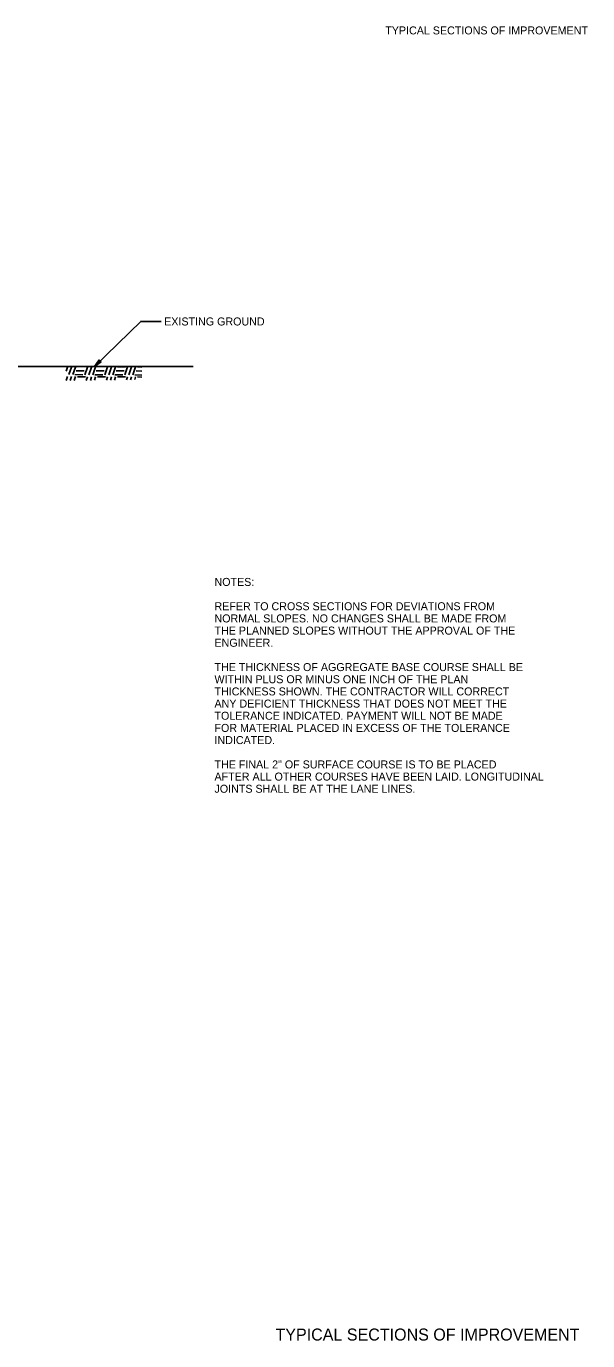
# Model space of a CAD drawing. Extents: x 1824008 to 1828864, y 689441 to 689870.
# Drawn here: x 1828822.3 to 1828864.4, y 689441.4 to 689539.9 of the extents above; entities that cross this region are included whole.
import ezdxf

# ---------------------------------------------------------------- set-up
doc = ezdxf.new("R2010")
doc.units = 0
for name, color, linetype in [('1', 7, 'Continuous'), ('19', 7, 'Continuous'), ('42', 7, 'Continuous'), ('R_Draft', 7, 'Continuous')]:
    doc.layers.add(name, color=color, linetype=linetype)

msp = doc.modelspace()

# ---------------------------------------------------------------- linework, layer by layer
at = {"layer": '1'}
for p, q in [((1828827.765, 689514.917), (1828827.406, 689514.426)), ((1828827.794, 689514.881), (1828827.511, 689514.548)), ((1828827.91, 689514.767), (1828827.765, 689514.917)), ((1828804.735, 689514.422), (1828834.812, 689514.422)), ((1828827.406, 689514.426), (1828827.91, 689514.767)), ((1828827.527, 689514.528), (1828827.869, 689514.802))]:
    msp.add_line(p, q, dxfattribs=at)
msp.add_lwpolyline([(1828832.42, 689517.791), (1828830.882, 689517.793), (1828827.407, 689514.425)], dxfattribs=at)
at = {"layer": '42'}
for p, q in [((1828825.28, 689514.066), (1828825.384, 689514.372)), ((1828825.492, 689513.804), (1828825.683, 689514.368)), ((1828825.792, 689513.803), (1828825.982, 689514.364)), ((1828826.043, 689514.101), (1828826.643, 689514.098)), ((1828826.692, 689513.798), (1828826.885, 689514.369)), ((1828826.992, 689513.797), (1828827.188, 689514.374)), ((1828827.292, 689513.795), (1828827.49, 689514.378)), ((1828827.543, 689514.094), (1828828.143, 689514.091)), ((1828828.192, 689513.79), (1828828.395, 689514.389)), ((1828828.242, 689514.39), (1828828.245, 689514.39)), ((1828828.492, 689513.789), (1828828.695, 689514.388)), ((1828828.792, 689513.787), (1828828.995, 689514.386)), ((1828829.043, 689514.086), (1828829.643, 689514.083)), ((1828829.145, 689514.385), (1828829.745, 689514.382)), ((1828829.692, 689513.783), (1828829.895, 689514.382)), ((1828829.992, 689513.781), (1828830.195, 689514.38)), ((1828830.292, 689513.78), (1828830.495, 689514.378)), ((1828830.543, 689514.078), (1828830.954, 689514.076)), ((1828830.645, 689514.378), (1828830.955, 689514.376)), ((1828825.295, 689513.373), (1828825.391, 689513.655)), ((1828825.595, 689513.369), (1828825.691, 689513.653)), ((1828825.894, 689513.365), (1828825.991, 689513.652)), ((1828825.942, 689513.802), (1828826.542, 689513.799)), ((1828826.141, 689513.651), (1828826.741, 689513.648)), ((1828826.796, 689513.368), (1828826.891, 689513.647)), ((1828827.098, 689513.372), (1828827.191, 689513.646)), ((1828827.401, 689513.377), (1828827.491, 689513.644)), ((1828827.442, 689513.794), (1828828.042, 689513.791)), ((1828827.641, 689513.643), (1828828.191, 689513.64)), ((1828828.191, 689513.64), (1828828.241, 689513.64)), ((1828828.307, 689513.391), (1828828.391, 689513.639)), ((1828828.609, 689513.396), (1828828.691, 689513.638)), ((1828828.911, 689513.401), (1828828.991, 689513.636)), ((1828828.942, 689513.786), (1828829.542, 689513.783)), ((1828829.141, 689513.635), (1828829.741, 689513.632)), ((1828829.817, 689513.415), (1828829.891, 689513.632)), ((1828830.121, 689513.423), (1828830.191, 689513.63)), ((1828830.427, 689513.439), (1828830.491, 689513.628)), ((1828830.442, 689513.779), (1828830.952, 689513.776)), ((1828830.641, 689513.628), (1828830.952, 689513.626))]:
    msp.add_line(p, q, dxfattribs=at)

# ---------------------------------------------------------------- texts
at = {"layer": '1'}
msp.add_text('TYPICAL SECTIONS OF IMPROVEMENT', height=0.9, dxfattribs=at).set_placement((1828840.982, 689441.363))
at = {"layer": '19'}
for s, p in [('NOTES:', (1828836.406, 689497.958)), ('REFER TO CROSS SECTIONS FOR DEVIATIONS FROM', (1828836.406, 689496.133)), ('NORMAL SLOPES. NO CHANGES SHALL BE MADE FROM ', (1828836.406, 689495.221)), ('THE PLANNED SLOPES WITHOUT THE APPROVAL OF THE', (1828836.406, 689494.308)), ('ENGINEER.', (1828836.406, 689493.396)), ('WITHIN PLUS OR MINUS ONE INCH OF THE PLAN ', (1828836.406, 689490.658)), ('THE THICKNESS OF AGGREGATE BASE COURSE SHALL BE', (1828836.406, 689491.571)), ('THICKNESS SHOWN. THE CONTRACTOR WILL CORRECT', (1828836.406, 689489.746)), ('ANY DEFICIENT THICKNESS THAT DOES NOT MEET THE', (1828836.406, 689488.833)), ('TOLERANCE INDICATED. PAYMENT WILL NOT BE MADE', (1828836.406, 689487.921)), ('FOR MATERIAL PLACED IN EXCESS OF THE TOLERANCE', (1828836.406, 689487.008)), ('INDICATED.', (1828836.406, 689486.096)), ('THE FINAL 2" OF SURFACE COURSE IS TO BE PLACED', (1828836.406, 689484.271)), ('AFTER ALL OTHER COURSES HAVE BEEN LAID. LONGITUDINAL', (1828836.406, 689483.358)), ('JOINTS SHALL BE AT THE LANE LINES.', (1828836.406, 689482.446))]:
    msp.add_text(s, height=0.6, dxfattribs=at).set_placement(p)
at = {"layer": 'R_Draft'}
for s, p in [('TYPICAL SECTIONS OF IMPROVEMENT', (1828849.216, 689539.32)), ('EXISTING GROUND', (1828832.635, 689517.491))]:
    msp.add_text(s, height=0.6, dxfattribs=at).set_placement(p)

doc.saveas('drawing.dxf')
